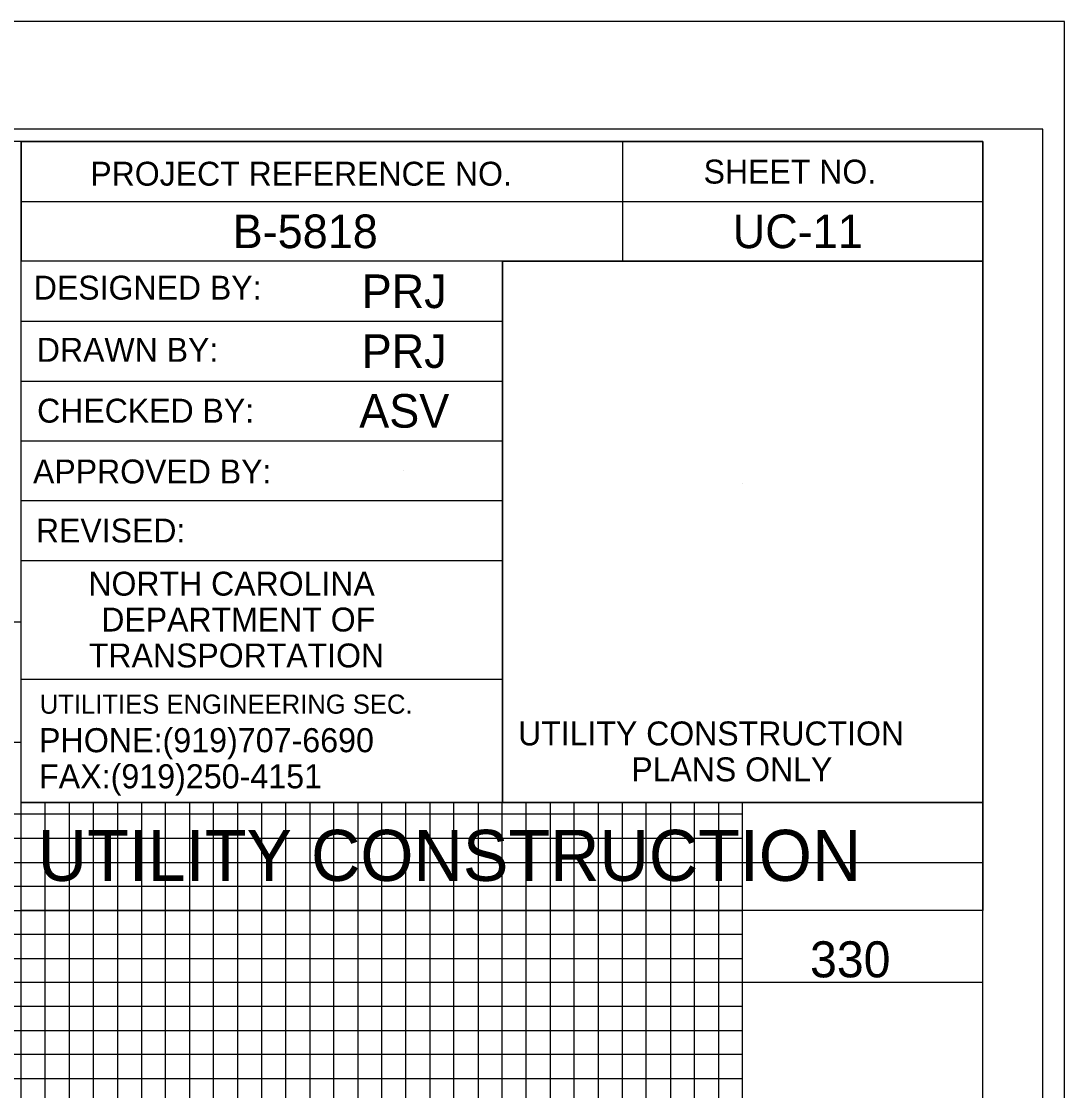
# Model space of a CAD drawing. Extents: x 3814791 to 3815465, y 1224203 to 1224643.
# Drawn here: x 3815378.1 to 3815464.9, y 1224554.2 to 1224643.2 of the extents above; entities that cross this region are included whole.
import ezdxf

# ---------------------------------------------------------------- set-up
doc = ezdxf.new("R2010")
doc.units = 0
for name, color, linetype in [('Exist Roads EOP', 7, 'Continuous'), ('General Text and Text Box and Leader Line', 7, 'Continuous'), ('Pattern 49', 7, 'Continuous'), ('Prop 8 In Water Line (St)', 7, 'Continuous'), ('Scratch_Level_1', 7, 'Continuous'), ('Scratch_Level_9', 7, 'Continuous'), ('Sheet Data Field CELL', 7, 'Continuous'), ('UC Full Profile Sheet 34 CELL', 7, 'Continuous')]:
    doc.layers.add(name, color=color, linetype=linetype)

msp = doc.modelspace()

# ---------------------------------------------------------------- linework, layer by layer
at = {"layer": 'Exist Roads EOP'}
for p, q in [((3815378.107, 1224623.187), (3815378.132, 1224633.207)), ((3815378.132, 1224633.207), (3815458.107, 1224633.207)), ((3815378.132, 1224623.252), (3815378.132, 1224633.207)), ((3815428.137, 1224633.187), (3815428.137, 1224623.232)), ((3815458.107, 1224633.207), (3815458.107, 1224623.252)), ((3815378.132, 1224628.212), (3815458.127, 1224628.212)), ((3815403.128, 1224625.731), (3815403.128, 1224625.731)), ((3815443.122, 1224625.732), (3815443.122, 1224625.732)), ((3815458.107, 1224623.252), (3815378.132, 1224623.252)), ((3815409.937, 1224620.742), (3815409.937, 1224620.742)), ((3815378.132, 1224618.252), (3815418.137, 1224618.252)), ((3815409.937, 1224615.762), (3815409.937, 1224615.762)), ((3815378.132, 1224613.272), (3815418.137, 1224613.272)), ((3815409.937, 1224610.787), (3815409.937, 1224610.787)), ((3815378.132, 1224608.292), (3815418.137, 1224608.292)), ((3815409.937, 1224605.807), (3815409.937, 1224605.807)), ((3815438.127, 1224604.747), (3815438.127, 1224604.747)), ((3815378.132, 1224603.317), (3815418.137, 1224603.317)), ((3815378.132, 1224598.332), (3815418.137, 1224598.332)), ((3815378.132, 1224588.457), (3815418.137, 1224588.457)), ((3815438.107, 1224561.207), (3814878.107, 1224561.207)), ((3814878.107, 1224559.207), (3815438.107, 1224559.207))]:
    msp.add_line(p, q, dxfattribs=at)
for points in [[(3815458.107, 1224633.207), (3814858.107, 1224633.207), (3814858.107, 1224213.207), (3815458.107, 1224213.207)], [(3814878.107, 1224633.207), (3814878.107, 1224223.207), (3815438.107, 1224223.207), (3815438.107, 1224578.187), (3815378.107, 1224578.187), (3815378.107, 1224633.207)], [(3815418.137, 1224623.252), (3815458.107, 1224623.252), (3815458.107, 1224578.187), (3815418.137, 1224578.187)]]:
    msp.add_lwpolyline(points, close=True, dxfattribs=at)
for points in [[(3815378.107, 1224223.207), (3815378.107, 1224633.207), (3815388.627, 1224633.207)], [(3815418.137, 1224623.252), (3815418.137, 1224578.187), (3815378.107, 1224578.187), (3815378.107, 1224633.207), (3815418.137, 1224633.207), (3815418.137, 1224633.147)], [(3815378.087, 1224593.207), (3814858.107, 1224593.207), (3814858.107, 1224573.187), (3815458.107, 1224573.187)], [(3815458.107, 1224563.207), (3814858.107, 1224563.207), (3814858.107, 1224583.207), (3815378.087, 1224583.207)], [(3815380.107, 1224223.207), (3815380.107, 1224578.187)], [(3815382.107, 1224578.187), (3815382.107, 1224223.207), (3815384.107, 1224223.207), (3815384.107, 1224578.187)], [(3815386.107, 1224578.187), (3815386.107, 1224223.207), (3815390.107, 1224223.207), (3815390.107, 1224578.187)], [(3815388.107, 1224578.187), (3815388.107, 1224223.207), (3815408.107, 1224223.207), (3815408.107, 1224578.187)], [(3815392.107, 1224578.187), (3815392.107, 1224223.207), (3815394.107, 1224223.207), (3815394.107, 1224578.187)], [(3815396.107, 1224578.187), (3815396.107, 1224223.207), (3815400.107, 1224223.207), (3815400.107, 1224578.187)], [(3815398.107, 1224578.187), (3815398.107, 1224223.207), (3815418.107, 1224223.207), (3815418.107, 1224578.187)], [(3815402.107, 1224578.187), (3815402.107, 1224223.207), (3815404.107, 1224223.207), (3815404.107, 1224578.187)], [(3815406.107, 1224578.187), (3815406.107, 1224223.207), (3815410.107, 1224223.207), (3815410.107, 1224578.187)], [(3815412.107, 1224578.187), (3815412.107, 1224223.207)], [(3815412.107, 1224223.207), (3815414.107, 1224223.207), (3815414.107, 1224578.187)], [(3815416.107, 1224578.187), (3815416.107, 1224223.207), (3815420.107, 1224223.207), (3815420.107, 1224578.187)], [(3815422.107, 1224578.187), (3815422.107, 1224223.207), (3815424.107, 1224223.207), (3815424.107, 1224578.187)], [(3815426.107, 1224578.187), (3815426.107, 1224223.207), (3815430.107, 1224223.207), (3815430.107, 1224578.187)], [(3815428.107, 1224578.187), (3815428.107, 1224223.207)], [(3815432.107, 1224578.187), (3815432.107, 1224223.207), (3815434.107, 1224223.207), (3815434.107, 1224578.187)], [(3815436.107, 1224578.187), (3815436.107, 1224223.207), (3815440.107, 1224223.207)], [(3815438.107, 1224577.207), (3814878.107, 1224577.207), (3814878.107, 1224577.207), (3814878.107, 1224569.207), (3815438.107, 1224569.207)], [(3814878.107, 1224575.207), (3815438.107, 1224575.207)], [(3815438.107, 1224571.207), (3814878.107, 1224571.207)], [(3815438.107, 1224567.207), (3814878.107, 1224567.207), (3814878.107, 1224565.207), (3815438.107, 1224565.207)], [(3815438.107, 1224557.207), (3814878.107, 1224557.207), (3814878.107, 1224555.207), (3815438.107, 1224555.207)]]:
    msp.add_lwpolyline(points, dxfattribs=at)
at = {"layer": 'Pattern 49'}
msp.add_lwpolyline([(3815463.107, 1224634.227), (3814796.507, 1224634.227), (3814796.507, 1224212.187), (3815463.107, 1224212.187)], close=True, dxfattribs=at)
at = {"layer": 'Scratch_Level_1'}
msp.add_lwpolyline([(3815464.907, 1224643.207), (3814791.307, 1224643.207), (3814791.307, 1224203.207), (3815464.907, 1224203.207)], close=True, dxfattribs=at)
at = {"layer": 'Sheet Data Field CELL'}
msp.add_lwpolyline([(3815378.107, 1224578.187), (3815458.107, 1224578.187), (3815458.107, 1224569.207), (3815378.107, 1224569.207)], close=True, dxfattribs=at)
at = {"layer": 'UC Full Profile Sheet 34 CELL'}
msp.add_lwpolyline([(3815378.107, 1224578.187), (3815458.107, 1224578.187), (3815458.107, 1224569.207), (3815416.023, 1224569.207), (3815402.086, 1224569.207), (3815378.107, 1224569.207)], close=True, dxfattribs=at)

# ---------------------------------------------------------------- texts
at = {"layer": 'Exist Roads EOP'}
for s, height, p in [('PROJECT REFERENCE NO.', 1.99161, (3815383.852, 1224629.532)), ('SHEET NO.', 1.9916, (3815434.877, 1224629.707)), ('DESIGNED BY:', 1.99161, (3815379.152, 1224620.047)), ('DRAWN BY:', 1.9916, (3815379.407, 1224614.872)), ('CHECKED BY:', 1.99161, (3815379.427, 1224609.807)), ('APPROVED BY:', 1.99161, (3815379.087, 1224604.747)), ('REVISED:', 1.9916, (3815379.327, 1224599.832)), ('NORTH CAROLINA', 1.99161, (3815383.692, 1224595.407)), ('DEPARTMENT OF', 1.99161, (3815384.767, 1224592.422)), ('TRANSPORTATION', 1.99161, (3815383.732, 1224589.432)), ('UTILITIES ENGINEERING SEC.', 1.59329, (3815379.647, 1224585.58)), ('UTILITY CONSTRUCTION', 1.99161, (3815419.442, 1224582.942)), ('PLANS ONLY', 1.9916, (3815428.857, 1224579.952))]:
    msp.add_text(s, height=height, rotation=360, dxfattribs=at).set_placement(p)
at = {"layer": 'General Text and Text Box and Leader Line'}
msp.add_text('330', height=3, dxfattribs=at).set_placement((3815443.729, 1224563.635))
at = {"layer": 'Prop 8 In Water Line (St)'}
for s, p in [('B-5818', (3815395.697, 1224624.331)), ('UC-11', (3815437.298, 1224624.332)), ('PRJ', (3815406.429, 1224619.342)), ('PRJ', (3815406.429, 1224614.362)), ('ASV', (3815406.224, 1224609.387))]:
    msp.add_text(s, height=2.8, dxfattribs=at).set_placement(p)
at = {"layer": 'Scratch_Level_9'}
for s, p in [('PHONE:(919)707-6690', (3815379.586, 1224582.373)), ('FAX:(919)250-4151', (3815379.586, 1224579.368))]:
    msp.add_text(s, height=2.00457, rotation=360, dxfattribs=at).set_placement(p)
at = {"layer": 'Sheet Data Field CELL'}
msp.add_text('UTILITY CONSTRUCTION', height=4.25, rotation=360, dxfattribs=at).set_placement((3815379.478, 1224571.662))

doc.saveas('drawing.dxf')
